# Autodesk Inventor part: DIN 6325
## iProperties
Company: Bakker Hydraulic B.V.
Shininess: 64.0
Length Units: 11269
Angle Units: 11279
Time Units: 11290
Mass Units: 11283
Length Display Precision: 3
Angle Display Precision: 2
Compacted: True
Part Number: DIN 6325
Document SubType Name: Modeling
Created: 2003-01
Cost Center: 0.0 kg
Designer: Cor J. de Vlaming
Authority: 3025.74777 mm^3
Engineer: Cor de Vlaming
Description: DIN 6325 / ISO 8734 - Ø10 x 40
Material: Staal gehard
Project: Dowel Pins
Density: 0.0
Volumn: 0.0
Area: 0.0
PropertySet Name: Model Information
Control State: 0
Master: False
Checked Out: False
SaveDate: 2003-01-07
SaveTime: 13:22
TotalMass: 0.0 kg
TotalVolume: 3025.74777 mm^3
Author: Cor J. de Vlaming
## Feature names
1. Revolution1
